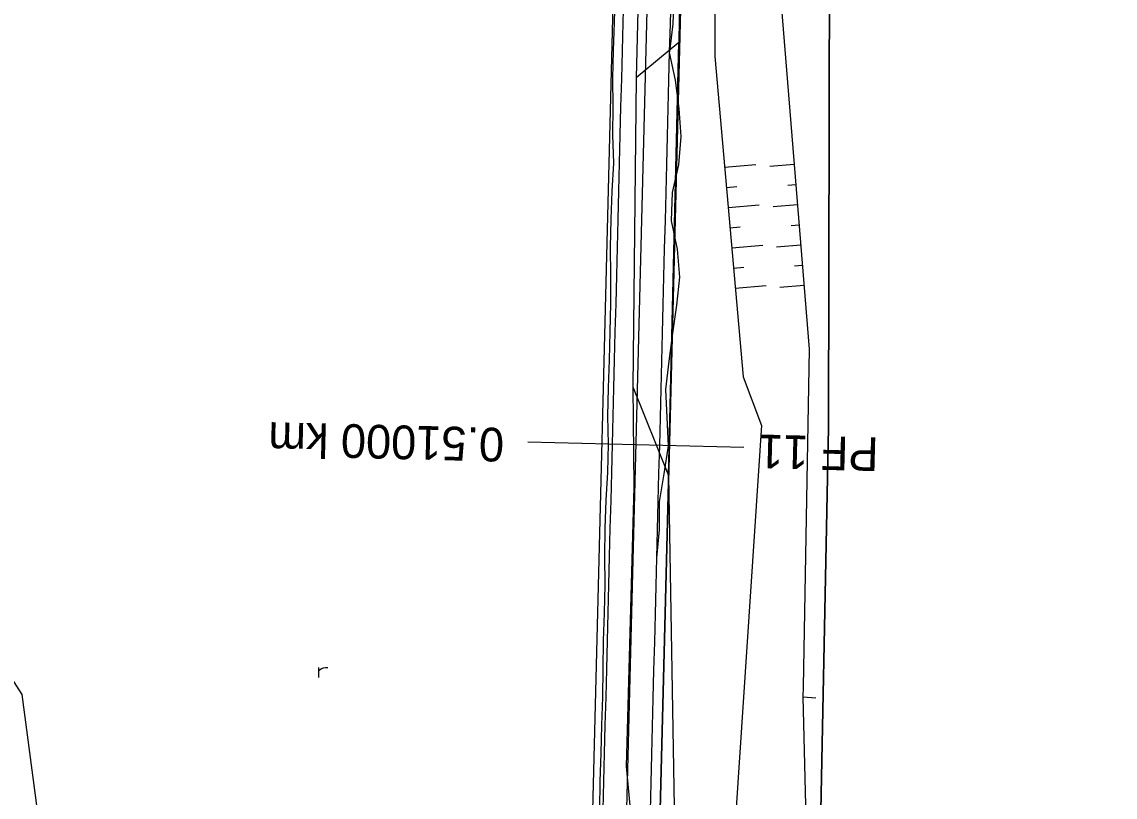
# Model space of a CAD drawing. Extents: x -555887 to -552101, y -1100251 to -1096546.
# Drawn here: x -553960.9 to -553879.9, y -1098102.3 to -1098044.9 of the extents above; entities that cross this region are included whole.
import ezdxf

# ---------------------------------------------------------------- set-up
doc = ezdxf.new("R2010")
doc.units = 0
for name, color, linetype in [('07_KANALIZACE', 7, 'Continuous'), ('PARCELY_cesty', 7, 'Continuous'), ('PARCELY_VHO', 7, 'Continuous'), ('POLYGONY_SITUACE_PF', 7, 'Continuous'), ('POLYGONY_SITUACE_PF_POPISY', 7, 'Continuous'), ('POLYGONY_SITUACE_PO', 7, 'Continuous'), ('ZSST', 7, 'Continuous'), ('zájem', 7, 'Continuous')]:
    doc.layers.add(name, color=color, linetype=linetype)

msp = doc.modelspace()

# ---------------------------------------------------------------- linework, layer by layer
at = {"layer": '07_KANALIZACE'}
msp.add_lwpolyline([(-553933.89, -1098299.13), (-553960.89, -1098094.71), (-553961.69, -1098093.49), (-553975.36, -1098088.42), (-553976.47, -1098087.2), (-553997.02, -1097931.32), (-553999.16, -1097907.75), (-553999.72, -1097884.17), (-554000.634, -1097884.273), (-554001.151, -1097883.391), (-554017.16, -1097885.22), (-554171.94, -1097905.19), (-554183.71, -1097906.5), (-554193.28, -1097906.43), (-554202.55, -1097905.69), (-554209.215, -1097906.283), (-554215.09, -1097906.8), (-554226.01, -1097910.87), (-554237.13, -1097913.33)], dxfattribs=at)
at = {"layer": 'PARCELY_cesty'}
for points in [[(-553894.521, -1098237.552), (-553902.872, -1098185.471), (-553908.173, -1098161.777), (-553915.637, -1098135.941), (-553917.674, -1098126.716), (-553918.832, -1098111.157), (-553915.214, -1097968.237), (-553915.615, -1097956.495), (-553918.446, -1097924.391)], [(-553889.599, -1098236.663), (-553897.959, -1098184.529), (-553903.327, -1098160.536), (-553910.789, -1098134.707), (-553912.715, -1098125.988), (-553913.828, -1098111.034), (-553910.368, -1097974.94), (-553910.211, -1097968.215), (-553910.622, -1097956.19), (-553913.42, -1097924.46)]]:
    msp.add_lwpolyline(points, dxfattribs=at)
at = {"layer": 'PARCELY_VHO'}
for points in [[(-553927.41, -1097628.08), (-553920.29, -1097651.1), (-553924.15, -1097670.8), (-553927.014, -1097685.697), (-553927.942, -1097698.335), (-553926.88, -1097721.034), (-553926.037, -1097728.701), (-553924.494, -1097736.179), (-553911.111, -1097775.519), (-553905.076, -1097799.369), (-553903.199, -1097814.131), (-553902.803, -1097824.091), (-553903.498, -1097838.889), (-553913.42, -1097924.2), (-553904.91, -1097952.6), (-553904.09, -1097966.52), (-553910.368, -1097974.94), (-553913.828, -1098111.034), (-553912.715, -1098125.988), (-553910.789, -1098134.707), (-553870.98, -1098223.96)], [(-553873.38, -1098200.91), (-553884.8, -1098171.23), (-553894.57, -1098145.41), (-553899.89, -1098126.48), (-553901.66, -1098118.62), (-553901.87, -1098110.72), (-553901.16, -1098074.95), (-553900.96, -1097982.79), (-553898.75, -1097974.9), (-553895.85, -1097967.85), (-553895.42, -1097963.37), (-553895.17, -1097959.49), (-553895.01, -1097951.32), (-553903.94, -1097924.64)]]:
    msp.add_lwpolyline(points, dxfattribs=at)
at = {"layer": 'POLYGONY_SITUACE_PF'}
for p, q in [((-553915.447, -1098076.218), (-553923.444, -1098076.015)), ((-553907.449, -1098076.42), (-553915.447, -1098076.218))]:
    msp.add_line(p, q, dxfattribs=at)
at = {"layer": 'POLYGONY_SITUACE_PO'}
for p, q in [((-553912.713, -1097968.226), (-553916.33, -1098111.096)), ((-553916.977, -1098042.835), (-553917.052, -1098044.917)), ((-553916.353, -1098042.851), (-553916.405, -1098044.934)), ((-553916.353, -1098042.851), (-553916.405, -1098044.934)), ((-553912.854, -1098042.94), (-553912.906, -1098045.022)), ((-553912.854, -1098042.94), (-553912.906, -1098045.022)), ((-553912.615, -1098042.946), (-553912.697, -1098045.028)), ((-553917.052, -1098044.917), (-553917.13, -1098046.999)), ((-553916.405, -1098044.934), (-553916.458, -1098047.016)), ((-553916.405, -1098044.934), (-553916.458, -1098047.016)), ((-553912.906, -1098045.022), (-553912.959, -1098047.105)), ((-553912.906, -1098045.022), (-553912.959, -1098047.105)), ((-553912.697, -1098045.028), (-553912.949, -1098047.105)), ((-553917.13, -1098046.999), (-553917.168, -1098049.082)), ((-553916.458, -1098047.016), (-553916.511, -1098049.099)), ((-553916.458, -1098047.016), (-553916.511, -1098049.099)), ((-553912.959, -1098047.105), (-553913.012, -1098049.188)), ((-553912.959, -1098047.105), (-553913.012, -1098049.188)), ((-553912.949, -1098047.105), (-553912.96, -1098047.147)), ((-553912.96, -1098047.147), (-553912.53, -1098049.2)), ((-553917.168, -1098049.082), (-553917.132, -1098051.167)), ((-553916.511, -1098049.099), (-553916.564, -1098051.182)), ((-553916.511, -1098049.099), (-553916.564, -1098051.182)), ((-553913.012, -1098049.188), (-553913.065, -1098051.27)), ((-553913.012, -1098049.188), (-553913.065, -1098051.27)), ((-553912.53, -1098049.2), (-553912.248, -1098051.291)), ((-553917.132, -1098051.167), (-553917.167, -1098053.25)), ((-553916.564, -1098051.182), (-553916.616, -1098053.264)), ((-553916.564, -1098051.182), (-553916.616, -1098053.264)), ((-553913.065, -1098051.27), (-553913.117, -1098053.353)), ((-553913.065, -1098051.27), (-553913.117, -1098053.353)), ((-553912.248, -1098051.291), (-553912.109, -1098053.378)), ((-553917.167, -1098053.25), (-553917.086, -1098055.336)), ((-553916.616, -1098053.264), (-553916.669, -1098055.347)), ((-553916.616, -1098053.264), (-553916.669, -1098055.347)), ((-553913.117, -1098053.353), (-553913.17, -1098055.436)), ((-553913.117, -1098053.353), (-553913.17, -1098055.436)), ((-553912.109, -1098053.378), (-553912.279, -1098055.458)), ((-553917.086, -1098055.336), (-553917.219, -1098057.417)), ((-553916.669, -1098055.347), (-553916.722, -1098057.43)), ((-553916.669, -1098055.347), (-553916.722, -1098057.43)), ((-553913.17, -1098055.436), (-553913.223, -1098057.518)), ((-553913.17, -1098055.436), (-553913.223, -1098057.518)), ((-553912.279, -1098055.458), (-553912.753, -1098057.53)), ((-553917.219, -1098057.417), (-553917.289, -1098059.499)), ((-553916.722, -1098057.43), (-553916.774, -1098059.512)), ((-553916.722, -1098057.43), (-553916.774, -1098059.512)), ((-553913.223, -1098057.518), (-553913.276, -1098059.601)), ((-553913.223, -1098057.518), (-553913.276, -1098059.601)), ((-553912.753, -1098057.53), (-553912.819, -1098059.613)), ((-553917.289, -1098059.499), (-553917.33, -1098061.582)), ((-553916.774, -1098059.512), (-553916.827, -1098061.595)), ((-553916.774, -1098059.512), (-553916.827, -1098061.595)), ((-553913.276, -1098059.601), (-553913.328, -1098061.684)), ((-553913.276, -1098059.601), (-553913.328, -1098061.684)), ((-553912.819, -1098059.613), (-553912.365, -1098061.708)), ((-553917.33, -1098061.582), (-553917.326, -1098063.666)), ((-553916.827, -1098061.595), (-553916.88, -1098063.678)), ((-553916.827, -1098061.595), (-553916.88, -1098063.678)), ((-553913.328, -1098061.684), (-553913.381, -1098063.766)), ((-553913.328, -1098061.684), (-553913.381, -1098063.766)), ((-553912.365, -1098061.708), (-553912.203, -1098063.796)), ((-553917.326, -1098063.666), (-553917.307, -1098065.751)), ((-553916.88, -1098063.678), (-553916.933, -1098065.76)), ((-553916.88, -1098063.678), (-553916.933, -1098065.76)), ((-553913.381, -1098063.766), (-553913.434, -1098065.849)), ((-553913.381, -1098063.766), (-553913.434, -1098065.849)), ((-553912.203, -1098063.796), (-553912.435, -1098065.874)), ((-553917.307, -1098065.751), (-553917.364, -1098067.833)), ((-553916.933, -1098065.76), (-553916.985, -1098067.843)), ((-553916.933, -1098065.76), (-553916.985, -1098067.843)), ((-553913.434, -1098065.849), (-553913.487, -1098067.932)), ((-553913.434, -1098065.849), (-553913.487, -1098067.932)), ((-553912.435, -1098065.874), (-553912.711, -1098067.951)), ((-553917.364, -1098067.833), (-553917.427, -1098069.916)), ((-553916.985, -1098067.843), (-553917.038, -1098069.926)), ((-553916.985, -1098067.843), (-553917.038, -1098069.926)), ((-553913.487, -1098067.932), (-553913.539, -1098070.014)), ((-553913.487, -1098067.932), (-553913.539, -1098070.014)), ((-553912.711, -1098067.951), (-553912.988, -1098070.028)), ((-553917.427, -1098069.916), (-553917.482, -1098071.998)), ((-553917.038, -1098069.926), (-553917.091, -1098072.008)), ((-553917.038, -1098069.926), (-553917.091, -1098072.008)), ((-553913.539, -1098070.014), (-553913.592, -1098072.097)), ((-553913.539, -1098070.014), (-553913.592, -1098072.097)), ((-553912.988, -1098070.028), (-553913.235, -1098072.106)), ((-553917.482, -1098071.998), (-553917.538, -1098074.081)), ((-553917.091, -1098072.008), (-553917.144, -1098074.091)), ((-553917.091, -1098072.008), (-553917.144, -1098074.091)), ((-553913.592, -1098072.097), (-553913.645, -1098074.18)), ((-553913.592, -1098072.097), (-553913.645, -1098074.18)), ((-553913.235, -1098072.106), (-553913.144, -1098074.192)), ((-553917.538, -1098074.081), (-553917.488, -1098076.166)), ((-553917.144, -1098074.091), (-553917.196, -1098076.174)), ((-553917.144, -1098074.091), (-553917.196, -1098076.174)), ((-553913.645, -1098074.18), (-553913.697, -1098076.262)), ((-553913.645, -1098074.18), (-553913.697, -1098076.262)), ((-553913.144, -1098074.192), (-553913.043, -1098076.279)), ((-553917.488, -1098076.166), (-553917.55, -1098078.249)), ((-553917.196, -1098076.174), (-553917.249, -1098078.256)), ((-553917.196, -1098076.174), (-553917.249, -1098078.256)), ((-553913.697, -1098076.262), (-553913.75, -1098078.345)), ((-553913.697, -1098076.262), (-553913.75, -1098078.345)), ((-553913.043, -1098076.279), (-553913.374, -1098078.354)), ((-553917.55, -1098078.249), (-553917.659, -1098080.33)), ((-553917.249, -1098078.256), (-553917.302, -1098080.339)), ((-553917.249, -1098078.256), (-553917.302, -1098080.339)), ((-553913.75, -1098078.345), (-553913.803, -1098080.428)), ((-553913.75, -1098078.345), (-553913.803, -1098080.428)), ((-553913.374, -1098078.354), (-553913.715, -1098080.43)), ((-553917.659, -1098080.33), (-553917.747, -1098082.412)), ((-553917.302, -1098080.339), (-553917.355, -1098082.422)), ((-553917.302, -1098080.339), (-553917.355, -1098082.422)), ((-553913.803, -1098080.428), (-553913.856, -1098082.51)), ((-553913.803, -1098080.428), (-553913.856, -1098082.51)), ((-553913.715, -1098080.43), (-553913.72, -1098082.514)), ((-553917.747, -1098082.412), (-553917.759, -1098084.495)), ((-553917.355, -1098082.422), (-553917.407, -1098084.504)), ((-553917.355, -1098082.422), (-553917.407, -1098084.504)), ((-553913.856, -1098082.51), (-553913.908, -1098084.593)), ((-553913.856, -1098082.51), (-553913.908, -1098084.593)), ((-553913.72, -1098082.514), (-553913.908, -1098084.593)), ((-553917.759, -1098084.495), (-553917.738, -1098086.58)), ((-553917.407, -1098084.504), (-553917.46, -1098086.587)), ((-553917.407, -1098084.504), (-553917.46, -1098086.587)), ((-553913.908, -1098084.593), (-553913.961, -1098086.676)), ((-553913.908, -1098084.593), (-553913.961, -1098086.676)), ((-553913.908, -1098084.593), (-553913.961, -1098086.676)), ((-553913.908, -1098084.593), (-553913.908, -1098084.593)), ((-553917.738, -1098086.58), (-553917.777, -1098088.663)), ((-553917.46, -1098086.587), (-553917.513, -1098088.67)), ((-553917.46, -1098086.587), (-553917.513, -1098088.67)), ((-553913.961, -1098086.676), (-553914.014, -1098088.758)), ((-553913.961, -1098086.676), (-553914.014, -1098088.758)), ((-553913.961, -1098086.676), (-553914.014, -1098088.758)), ((-553917.777, -1098088.663), (-553917.854, -1098090.745)), ((-553917.513, -1098088.67), (-553917.565, -1098090.752)), ((-553917.513, -1098088.67), (-553917.565, -1098090.752)), ((-553914.014, -1098088.758), (-553914.067, -1098090.841)), ((-553914.014, -1098088.758), (-553914.067, -1098090.841)), ((-553914.014, -1098088.758), (-553914.067, -1098090.841)), ((-553917.854, -1098090.745), (-553917.879, -1098092.828)), ((-553917.565, -1098090.752), (-553917.618, -1098092.835)), ((-553917.565, -1098090.752), (-553917.618, -1098092.835)), ((-553914.067, -1098090.841), (-553914.119, -1098092.924)), ((-553914.067, -1098090.841), (-553914.119, -1098092.924)), ((-553914.067, -1098090.841), (-553914.119, -1098092.924)), ((-553917.879, -1098092.828), (-553917.921, -1098094.911)), ((-553917.618, -1098092.835), (-553917.671, -1098094.918)), ((-553917.618, -1098092.835), (-553917.671, -1098094.918)), ((-553914.119, -1098092.924), (-553914.172, -1098095.006)), ((-553914.119, -1098092.924), (-553914.172, -1098095.006)), ((-553914.119, -1098092.924), (-553914.172, -1098095.006)), ((-553917.921, -1098094.911), (-553917.992, -1098096.994)), ((-553917.671, -1098094.918), (-553917.724, -1098097)), ((-553917.671, -1098094.918), (-553917.724, -1098097)), ((-553914.172, -1098095.006), (-553914.225, -1098097.089)), ((-553914.172, -1098095.006), (-553914.225, -1098097.089)), ((-553914.172, -1098095.006), (-553914.225, -1098097.089)), ((-553917.992, -1098096.994), (-553918.026, -1098099.077)), ((-553917.724, -1098097), (-553917.776, -1098099.083)), ((-553917.724, -1098097), (-553917.776, -1098099.083)), ((-553914.225, -1098097.089), (-553914.278, -1098099.172)), ((-553914.225, -1098097.089), (-553914.278, -1098099.172)), ((-553914.225, -1098097.089), (-553914.278, -1098099.172)), ((-553918.026, -1098099.077), (-553918.095, -1098101.159)), ((-553917.776, -1098099.083), (-553917.829, -1098101.166)), ((-553917.776, -1098099.083), (-553917.829, -1098101.166)), ((-553914.278, -1098099.172), (-553914.33, -1098101.254)), ((-553914.278, -1098099.172), (-553914.33, -1098101.254)), ((-553914.278, -1098099.172), (-553914.33, -1098101.254)), ((-553918.095, -1098101.159), (-553918.143, -1098103.242)), ((-553917.829, -1098101.166), (-553917.882, -1098103.248)), ((-553917.829, -1098101.166), (-553917.882, -1098103.248)), ((-553914.33, -1098101.254), (-553914.383, -1098103.337)), ((-553914.33, -1098101.254), (-553914.383, -1098103.337)), ((-553914.33, -1098101.254), (-553914.383, -1098103.337))]:
    msp.add_line(p, q, dxfattribs=at)
at = {"layer": 'ZSST'}
for p, q in [((-553913.03, -1098078.48), (-553912.25, -1098046.41)), ((-553908.86, -1098055.648), (-553906.561, -1098055.446)), ((-553903.704, -1098055.452), (-553905.5, -1098055.598)), ((-553903.582, -1098056.947), (-553904.18, -1098056.995)), ((-553908.729, -1098057.142), (-553907.964, -1098057.075)), ((-553908.599, -1098058.636), (-553906.3, -1098058.435)), ((-553903.46, -1098058.442), (-553905.257, -1098058.588)), ((-553908.468, -1098060.13), (-553907.702, -1098060.063)), ((-553903.338, -1098059.937), (-553903.937, -1098059.985)), ((-553908.337, -1098061.625), (-553906.038, -1098061.423)), ((-553903.216, -1098061.432), (-553905.013, -1098061.578)), ((-553908.206, -1098063.119), (-553907.44, -1098063.052)), ((-553903.095, -1098062.927), (-553903.693, -1098062.975)), ((-553908.075, -1098064.613), (-553905.776, -1098064.412)), ((-553902.973, -1098064.422), (-553904.77, -1098064.568))]:
    msp.add_line(p, q, dxfattribs=at)
for points in [[(-553909.08, -1097888.54), (-553912.97, -1097925.48), (-553908.5, -1097951.76), (-553912.35, -1097977.16), (-553914.28, -1098003.09), (-553915.41, -1098049.02)], [(-553903.33, -1097964.72), (-553907.21, -1097972.49), (-553909.82, -1097977.03), (-553910.09, -1097985.04), (-553910.33, -1097998.84), (-553910.24, -1098015.04), (-553911.98, -1098027.76), (-553912.25, -1098046.41), (-553915.41, -1098049.02), (-553915.66, -1098071.91), (-553913.03, -1098078.48), (-553912.56, -1098105.97), (-553911.15, -1098124.85), (-553905.84, -1098151.19), (-553897.79, -1098154.47), (-553892.63, -1098170.29), (-553889.27, -1098181.07), (-553885.09, -1098178.58)], [(-553898.72, -1097972.09), (-553905.32, -1097983.06), (-553906.37, -1097989.18), (-553904.85, -1098009.74), (-553904.92, -1098040.52), (-553902.59, -1098069.12), (-553903.04, -1098094.15)], [(-553910.09, -1097985.04), (-553908.92, -1097997.81), (-553908.98, -1098015.37), (-553909.64, -1098027.89), (-553909.58, -1098047.43), (-553907.5, -1098071.18), (-553906.12, -1098074.78), (-553908.27, -1098107.21)], [(-553915.66, -1098071.91), (-553915.58, -1098079.33), (-553916.16, -1098100.06), (-553913.12, -1098132.4), (-553909.66, -1098145.85), (-553902.53, -1098166.3), (-553897.27, -1098194.21), (-553893.66, -1098223.05), (-553891.3, -1098238.44), (-553887.76, -1098249.7), (-553885.71, -1098256.03)], [(-553938.931, -1098093.453), (-553938.931, -1098092.721)], [(-553938.931, -1098092.957), (-553938.829, -1098092.862), (-553938.726, -1098092.799), (-553938.569, -1098092.752), (-553938.419, -1098092.729), (-553938.262, -1098092.721)], [(-553903.04, -1098094.15), (-553903.07, -1098094.9), (-553902.11, -1098094.97)], [(-553903.07, -1098094.9), (-553902.24, -1098129.02), (-553893.3, -1098154.98), (-553885.09, -1098178.58)]]:
    msp.add_lwpolyline(points, dxfattribs=at)
at = {"layer": 'zájem'}
for points in [[(-553903.94, -1097924.64), (-553895.01, -1097951.32), (-553895.17, -1097959.49), (-553895.42, -1097963.37), (-553895.85, -1097967.85), (-553898.75, -1097974.9), (-553900.96, -1097982.79), (-553901.16, -1098074.95), (-553901.87, -1098110.72), (-553901.66, -1098118.62), (-553899.89, -1098126.48), (-553894.57, -1098145.41), (-553884.8, -1098171.23), (-553873.38, -1098200.91)], [(-553873.38, -1098200.91), (-553884.8, -1098171.23), (-553894.57, -1098145.41), (-553899.89, -1098126.48), (-553901.66, -1098118.62), (-553901.87, -1098110.72), (-553901.16, -1098074.95), (-553900.96, -1097982.79), (-553898.75, -1097974.9), (-553895.85, -1097967.85), (-553895.42, -1097963.37), (-553895.17, -1097959.49), (-553895.01, -1097951.32), (-553903.94, -1097924.64)]]:
    msp.add_lwpolyline(points, dxfattribs=at)

# ---------------------------------------------------------------- texts
at = {"layer": 'POLYGONY_SITUACE_PF_POPISY'}
for s, p in [('0.51000 km', (-553925.171, -1098074.971)), ('PF 11', (-553897.427, -1098075.674))]:
    msp.add_text(s, height=2.5, rotation=178.54958, dxfattribs=at).set_placement(p)

doc.saveas('drawing.dxf')
